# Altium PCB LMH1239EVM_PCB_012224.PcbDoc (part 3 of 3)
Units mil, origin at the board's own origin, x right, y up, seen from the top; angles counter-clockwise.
Board outline 4000 x 4500 mil, 4 copper layers (Top Layer, L02_GND, L03_PWR, Bottom Layer), stack 61.395 mil thick; 161 components, 103 nets, 483 pads, 593 vias.
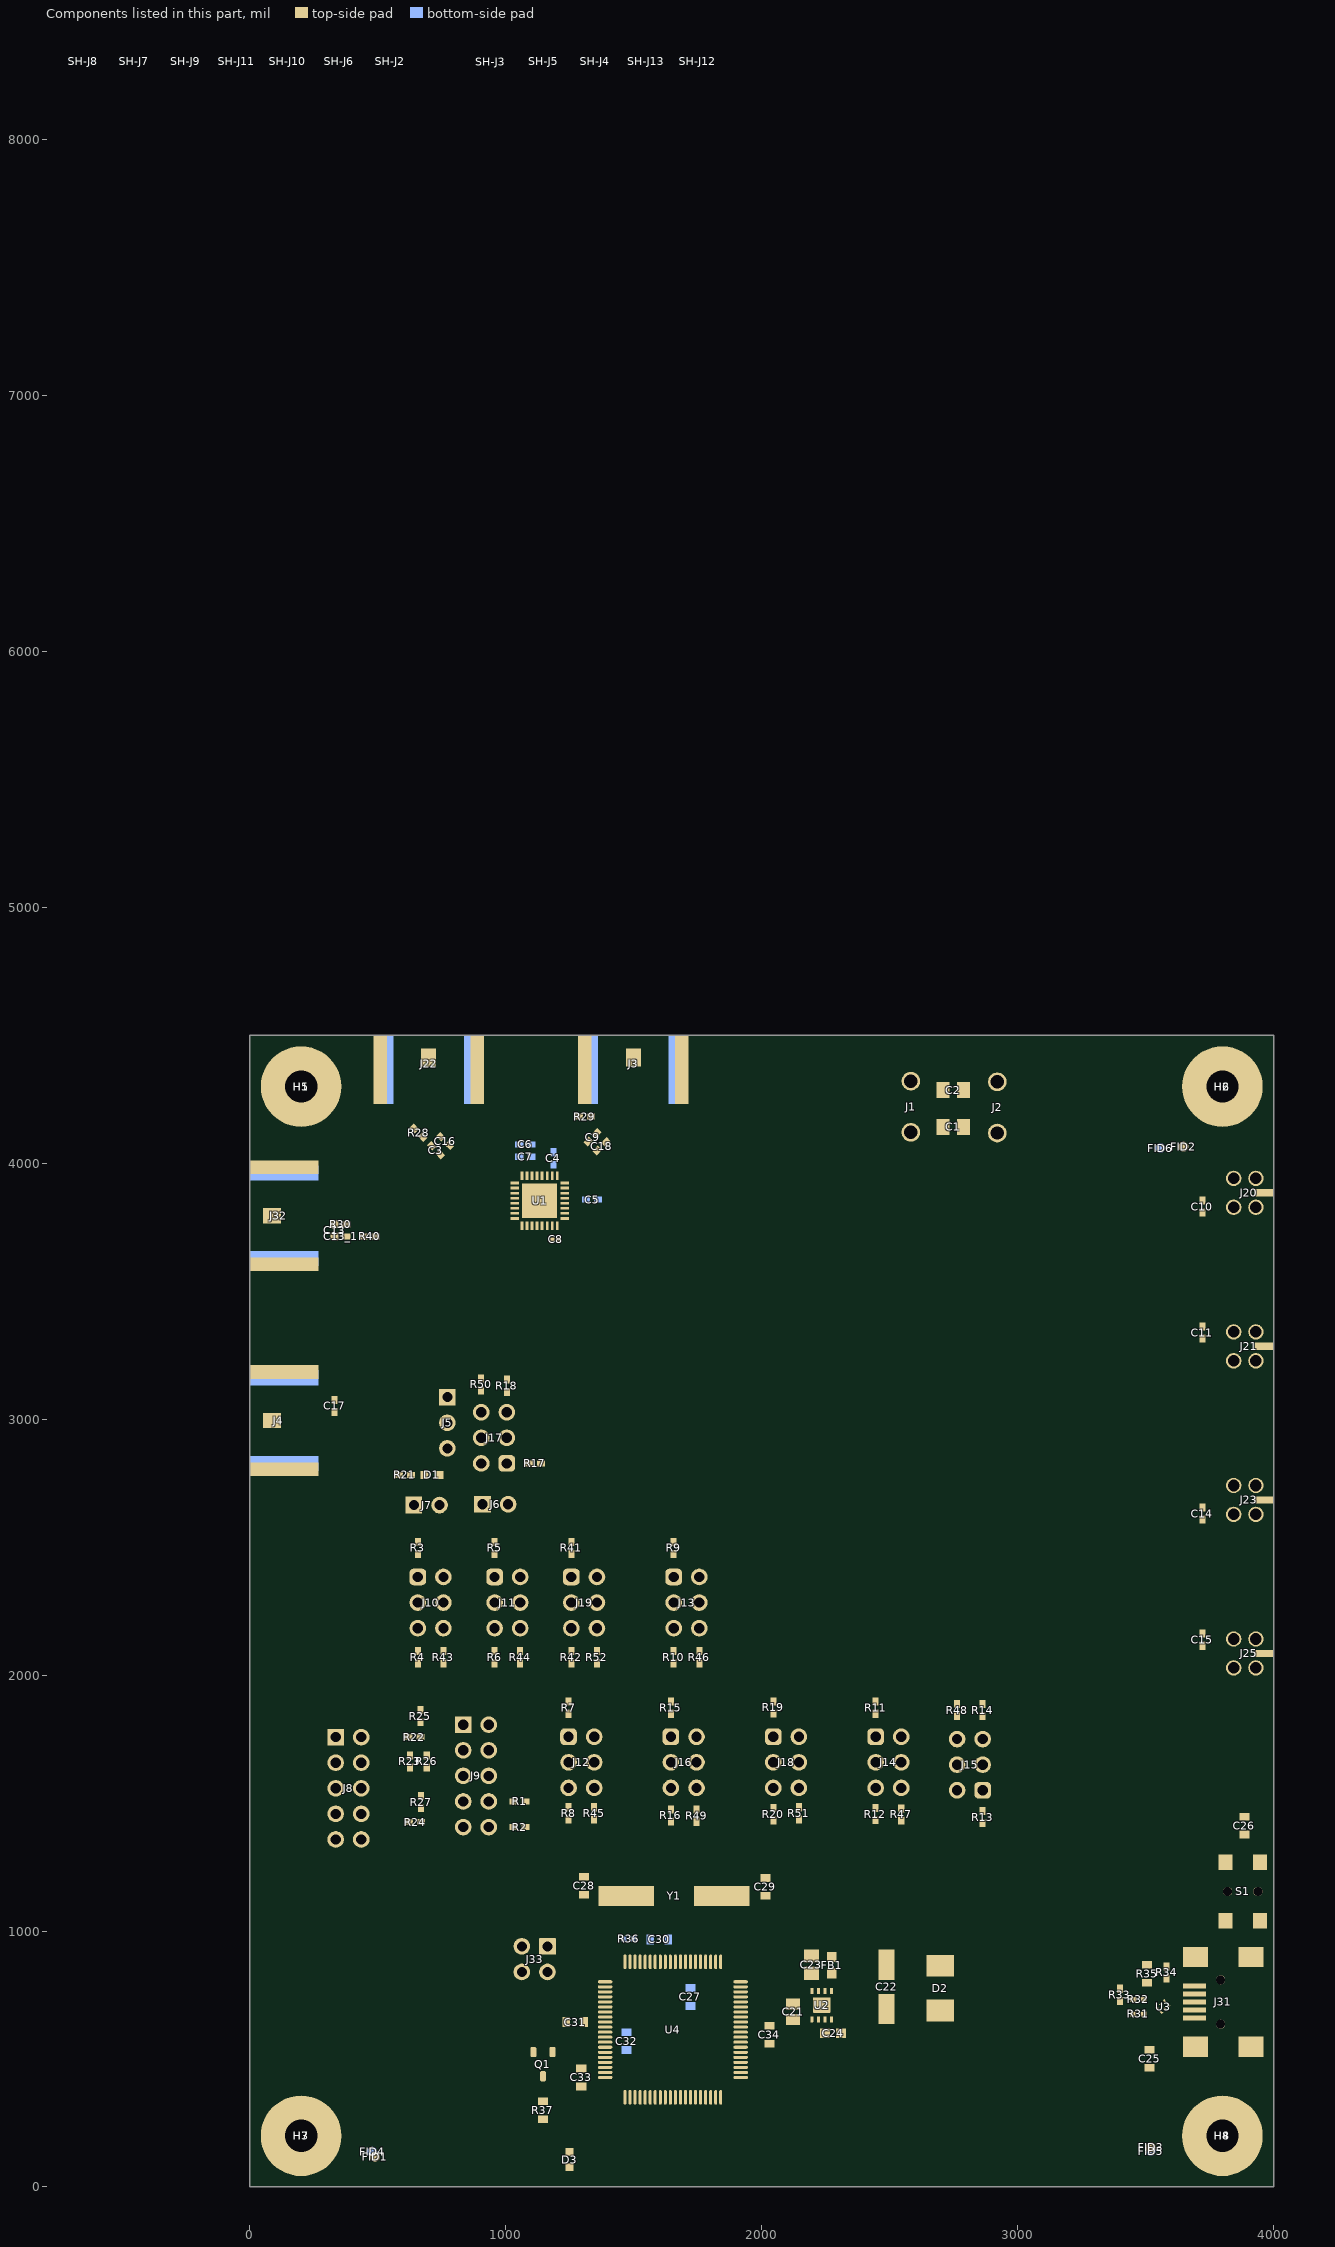
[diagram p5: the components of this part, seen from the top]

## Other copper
Top Layer:
  region net NetC17_2: 122.05,3024.71 122.05,3014.24 ccw(c139,3014.24) 139.8,2997.31 139.8,2993.03 ccw(c138.86,2976.25) 122.05,2976.28 122.05,2965.65 117.33,2965.65 cw(c117.33,2973.97) 109.02,2973.97 109.02,3011.68 cw(c122.05,3011.68)
  region net NetC13_2: 122.05,3824.71 122.05,3814.24 ccw(c139,3814.24) 139.8,3797.31 139.8,3793.03 ccw(c138.86,3776.25) 122.05,3776.28 122.05,3765.65 117.33,3765.65 cw(c117.33,3773.97) 109.02,3773.97 109.02,3811.68 cw(c122.05,3811.68)
  region net NetC16_2: 727.64,4377.95 717.18,4377.95 ccw(c717.18,4361) 700.25,4360.19 695.97,4360.19 ccw(c679.18,4361.13) 679.21,4377.94 668.59,4377.95 668.59,4382.66 cw(c676.9,4382.66) 676.9,4390.97 714.61,4390.97 cw(c714.61,4377.95)
  region net NetC18_2: 1527.64,4377.95 1517.18,4377.95 ccw(c1517.18,4361) 1500.25,4360.2 1495.97,4360.2 ccw(c1479.18,4361.14) 1479.21,4377.95 1468.59,4377.95 1468.59,4382.67 cw(c1476.9,4382.67) 1476.9,4390.98 1514.61,4390.98 cw(c1514.61,4377.95)
  region net VIN: 1212.58,3869.47 1293.89,3869.47 1298.54,3864.82 1298.54,3854.46 1292.78,3848.7 1278.57,3848.7 1268.83,3858.45 1212.58,3858.45
  region net OUT0_N: 3620.59,3570.56 3620.79,3581.36 3613.49,3580.36 3613.39,3571.56
  region net OUT0_P: 3620.59,3588.56 3620.79,3599.36 3613.49,3598.36 3613.39,3589.56
  pour cut-out: 1316.64,4213 1348.13,4213 1348.13,4153 1316.64,4153
  pour cut-out: 1206.28,3739.95 1206.28,3773.41 1175.57,3773.41 1175.57,3739.95
  pour cut-out: 1212.58,3799.4 1246.04,3799.4 1246.04,3830.1 1212.58,3830.1
  pour cut-out: 1212.58,3878.14 1246.04,3878.14 1246.04,3908.84 1212.58,3908.84
  pour cut-out: 1139.75,3932.76 1084.62,3932.76 1084.62,3970.36 1139.75,3970.36
  pour cut-out: 1015.63,3767.5 1015.63,3822.63 1053.23,3822.63 1053.23,3767.5
  pour cut-out: 1015.63,3885.61 1015.63,3940.74 1053.23,3940.74 1053.23,3885.61
  pour cut-out: 1171.97,3711.12 1216.14,3711.12 1216.14,3694.56 1171.97,3694.56
  pour cut-out: 665.25,4071.08 642.98,4093.35 685.41,4135.77 707.67,4113.5
  pour cut-out: 362.06,3744.64 393.55,3744.64 393.55,3684.64 362.06,3684.64
  pour cut-out: 428.27,3744.64 459.76,3744.64 459.76,3684.64 428.27,3684.64
  pour cut-out: 360.56,3091.47 360.56,3012.73 300.56,3012.73 300.56,3091.47
  pour cut-out: 360.56,3777.64 360.56,3698.89 300.56,3698.89 300.56,3777.64
  pour cut-out: 1422.97,4073.78 1367.29,4018.1 1324.86,4060.52 1380.54,4116.2
  pour cut-out: 1387.61,4109.13 1331.93,4053.45 1289.51,4095.88 1345.19,4151.56
  pour cut-out: 720.34,4100.84 776.02,4045.16 733.59,4002.74 677.91,4058.42
  pour cut-out: 755.69,4136.2 811.37,4080.52 768.95,4038.09 713.27,4093.77
  region net SDI_OUT+: 430.6,3392.33 430.52,3388.03 433.58,3388.45 433.61,3391.91
  region net VIN: 1147.53,3961.64 1147.53,3971.13 1161.78,3985.38 1166,3985.23 1171.49,3990.73 1171.49,3997.26 1166.46,4002.28 1156.27,4002.28 1136.05,3982.07 1136.05,3934.96 1147.53,3934.96 1147.53,3961.36
  region net VDD_LDO: 1077.13,3934.81 1077.13,3970.38 1071.76,3975.75 1049.35,3975.75 1030.68,3994.42 1030.68,4000.16 1035.03,4004.51 1057.09,4004.51 1088.16,3973.44 1088.16,3934.81
  region net VBUS: 3533.8,715.6 3525.86,715.56 3519.9,709.6 3519.9,701.4 3529.69,691.61 3544.43,691.63 3547.2,691.6 3553.5,697.9 3553.5,701.2 3539.1,715.6
  region net NetJ31_6: 3956.5,942 3583.4,942 3568.6,927.2 3568.6,847.2 3570.4,845.4 3834.3,845.4 3857.6,822.1 3857.6,626.1 3821.2,589.7 3642.2,589.7 3636.6,584.1 3636.6,509.3 3642.7,503.2 3642.7,502.5 3957,502.5 3970.9,516.4 3970.9,927.6
  region net NetC23_1: 2296,859 2293.51,861.49 2164.49,861.49 2162,859 2162,755 2165,752 2201,752 2202,753 2202,777.4 2210.8,786.2 2260.5,786.2 2266.1,780.6 2266.1,754.9 2267.7,753.3 2291.7,753.3 2296,757.6
  region net OUT1_N: 3620.59,2370.56 3620.79,2381.36 3613.49,2380.36 3613.39,2371.56
  region net OUT1_P: 3620.59,2388.56 3620.79,2399.36 3613.49,2398.36 3613.39,2389.56
  region net SDI_OUT-: 430.6,3402.33 430.52,3398.03 433.57,3398.45 433.61,3401.91
  region net GND: 534.56,4473.04 534.93,4473.4 534.93,4496.06 481.78,4496.06 481.78,4472.55 534.93,4472.55
  region net GND: 914.09,4473.04 914.45,4473.4 914.45,4496.06 861.31,4496.06 861.31,4472.55 914.45,4472.55
  region net GND: 2741.3,759.4 2459.1,759.4 2451.3,751.6 2451.3,617.1 2466.2,602.2 2740.1,602.2 2755.4,617.5 2755.4,745.3
  region net GND: 3620.6,775.3 3489,775.3 3481.15,783.15 3481.15,822.1 3490.85,831.8 3570.4,831.8 3733.6,831.8 3738.2,827.2 3738.2,776.6 3736.9,775.3
  region net GND: 3974.51,3124.93 3999.01,3124.93 3999.01,3262.81 3974.51,3262.81
  region net GND: 3974.51,3444.93 3999.01,3444.93 3999.01,3307.06 3974.51,3307.06
  region net GND: 3974.51,2244.94 3999.01,2244.94 3999.01,2107.06 3974.51,2107.06
  region net GND: 3974.51,1924.94 3999.01,1924.94 3999.01,2062.81 3974.51,2062.81
  region net GND: 3974.51,2524.94 3999.01,2524.94 3999.01,2662.81 3974.51,2662.81
  region net GND: 3974.51,2844.94 3999.01,2844.94 3999.01,2707.06 3974.51,2707.06
  region net 3P3V: 1979.95,592.45 1979.95,603.25 1997.6,620.9 1997.6,663.9 2011,677.3 2088.4,677.3 2178.6,677.3 2185.7,670.2 2198.9,670.2 2202.3,666.8 2202.3,604 2189.3,591 2007.5,591 2001,584.5 1987.9,584.5
  region: 124.03,2854.15 124.03,2865.18 124.03,2876.21
  pour cut-out: 3751.5,2670.69 3751.5,2591.94 3691.5,2591.94 3691.5,2670.69
  pour cut-out: 3751.5,2177.93 3751.5,2099.19 3691.5,2099.19 3691.5,2177.93
  pour cut-out: 3751.5,3377.93 3751.5,3299.19 3691.5,3299.19 3691.5,3377.93
  pour cut-out: 3751.5,3870.69 3751.5,3791.94 3691.5,3791.94 3691.5,3870.69
  text ".Layer_Name" at -923,-6999.16 h60
L02_GND:
  region net GND: 3968,2244.94 4000.01,2244.94 4000.01,2102.19 3968,2102.18
  region net GND: 3968,1924.94 4000.01,1924.94 4000.01,2067.69 3968,2067.69
  region net GND: 3968,2844.94 4000.01,2844.94 4000.01,2702.19 3968,2702.18
  region net GND: 3968,2524.94 4000.01,2524.94 4000.01,2667.69 3968,2667.69
  region net GND: 3968,3444.93 4000.01,3444.93 4000.01,3302.18 3968,3302.18
  region net GND: 3968,3124.93 4000.01,3124.93 4000.01,3267.68 3968,3267.69
  region net GND: 3968,3724.93 4000.01,3724.93 4000.01,3867.68 3968,3867.69
  region net GND: 3968,4044.93 4000.01,4044.93 4000.01,3902.18 3968,3902.18
  pour cut-out: 1316.64,4213 1348.13,4213 1348.13,4153 1316.64,4153
  pour cut-out: 1015.63,3885.61 1015.63,3940.74 1053.23,3940.74 1053.23,3885.61
  pour cut-out: 1015.63,3767.5 1015.63,3822.63 1053.23,3822.63 1053.23,3767.5
  pour cut-out: 1139.75,3932.76 1084.62,3932.76 1084.62,3970.36 1139.75,3970.36
  pour cut-out: 1212.58,3878.14 1246.04,3878.14 1246.04,3908.84 1212.58,3908.84
  pour cut-out: 1212.58,3799.4 1246.04,3799.4 1246.04,3830.1 1212.58,3830.1
  pour cut-out: 1206.28,3739.95 1206.28,3773.41 1175.57,3773.41 1175.57,3739.95
  pour cut-out: 1171.97,3711.12 1216.14,3711.12 1216.14,3694.56 1171.97,3694.56
  pour cut-out: 665.25,4071.08 642.98,4093.35 685.41,4135.77 707.67,4113.5
  pour cut-out: 362.06,3744.64 393.55,3744.64 393.55,3684.64 362.06,3684.64
  pour cut-out: 428.27,3744.64 459.76,3744.64 459.76,3684.64 428.27,3684.64
  pour cut-out: 360.56,3091.47 360.56,3012.73 300.56,3012.73 300.56,3091.47
  pour cut-out: 360.56,3777.64 360.56,3698.89 300.56,3698.89 300.56,3777.64
  pour cut-out: 1387.61,4109.13 1331.93,4053.45 1289.51,4095.88 1345.19,4151.56
  pour cut-out: 1422.97,4073.78 1367.29,4018.1 1324.86,4060.52 1380.54,4116.2
  pour cut-out: 755.69,4136.2 811.37,4080.52 768.95,4038.09 713.27,4093.77
  pour cut-out: 720.34,4100.84 776.02,4045.16 733.59,4002.74 677.91,4058.42
  pour cut-out: 3922,2067.69 3999,2067.69 3999,2102.19 3922,2102.19
  pour cut-out: 3922,3867.68 3999,3867.68 3999,3902.18 3922,3902.18
  pour cut-out: 3922,3267.68 3999,3267.68 3999,3302.18 3922,3302.18
  pour cut-out: 3922,2667.69 3999,2667.69 3999,2702.19 3922,2702.19
  pour cut-out: 3751.5,2177.93 3751.5,2099.19 3691.5,2099.19 3691.5,2177.93
  pour cut-out: 3751.5,2670.69 3751.5,2591.94 3691.5,2591.94 3691.5,2670.69
  pour cut-out: 3751.5,3870.69 3751.5,3791.94 3691.5,3791.94 3691.5,3870.69
  pour cut-out: 3751.5,3377.93 3751.5,3299.19 3691.5,3299.19 3691.5,3377.93
  text ".Layer_Name" at -897.39,-6995.96 h60
L03_PWR:
  region net GND: 3968,2244.94 4000.01,2244.94 4000.01,2102.19 3968,2102.18
  region net GND: 3968,1924.94 4000.01,1924.94 4000.01,2067.69 3968,2067.69
  region net GND: 3968,2844.94 4000.01,2844.94 4000.01,2702.19 3968,2702.18
  region net GND: 3968,2524.94 4000.01,2524.94 4000.01,2667.69 3968,2667.69
  region net GND: 3968,3444.93 4000.01,3444.93 4000.01,3302.18 3968,3302.18
  region net GND: 3968,3124.93 4000.01,3124.93 4000.01,3267.68 3968,3267.69
  region net GND: 3968,3724.93 4000.01,3724.93 4000.01,3867.68 3968,3867.69
  region net GND: 3968,4044.93 4000.01,4044.93 4000.01,3902.18 3968,3902.18
  pour cut-out: 1316.64,4213 1348.13,4213 1348.13,4153 1316.64,4153
  pour cut-out: 665.25,4071.08 642.98,4093.35 685.41,4135.77 707.67,4113.5
  pour cut-out: 362.06,3744.64 393.55,3744.64 393.55,3684.64 362.06,3684.64
  pour cut-out: 428.27,3744.64 459.76,3744.64 459.76,3684.64 428.27,3684.64
  pour cut-out: 3751.5,2177.93 3751.5,2099.19 3691.5,2099.19 3691.5,2177.93
  pour cut-out: 3751.5,2670.69 3751.5,2591.94 3691.5,2591.94 3691.5,2670.69
  pour cut-out: 3751.5,3377.93 3751.5,3299.19 3691.5,3299.19 3691.5,3377.93
  pour cut-out: 3751.5,3870.69 3751.5,3791.94 3691.5,3791.94 3691.5,3870.69
  pour cut-out: 360.56,3091.47 360.56,3012.73 300.56,3012.73 300.56,3091.47
  pour cut-out: 360.56,3777.64 360.56,3698.89 300.56,3698.89 300.56,3777.64
  pour cut-out: 1387.61,4109.13 1331.93,4053.45 1289.51,4095.88 1345.19,4151.56
  pour cut-out: 1422.97,4073.78 1367.29,4018.1 1324.86,4060.52 1380.54,4116.2
  pour cut-out: 755.69,4136.2 811.37,4080.52 768.95,4038.09 713.27,4093.77
  pour cut-out: 720.34,4100.84 776.02,4045.16 733.59,4002.74 677.91,4058.42
  pour cut-out: 3922,2067.69 3999,2067.69 3999,2102.19 3922,2102.19
  pour cut-out: 3922,3867.68 3999,3867.68 3999,3902.18 3922,3902.18
  pour cut-out: 3922,3267.68 3999,3267.68 3999,3302.18 3922,3302.18
  pour cut-out: 3922,2667.69 3999,2667.69 3999,2702.19 3922,2702.19
  text ".Layer_Name" at -929.4,-6999.16 h60
Bottom Layer:
  region net GND: 3968,2244.94 4000.01,2244.94 4000.01,2067.69 3968,2067.68
  region net GND: 3968,1924.94 4000.01,1924.94 4000.01,2067.69 3968,2067.69
  region net GND: 3968,2844.94 4000.01,2844.94 4000.01,2667.69 3968,2667.68
  region net GND: 3968,2524.94 4000.01,2524.94 4000.01,2667.69 3968,2667.69
  region net GND: 3968,3444.93 4000.01,3444.93 4000.01,3267.68 3968,3267.68
  region net GND: 3968,3124.93 4000.01,3124.93 4000.01,3267.68 3968,3267.69
  region net GND: 3968,3724.93 4000.01,3724.93 4000.01,3867.68 3968,3867.69
  region net GND: 3968,4044.93 4000.01,4044.93 4000.01,3867.68 3968,3867.68
  region net VIN: 1147.57,3973.3 1142.24,3978.63 1142.24,3988.4 1166.26,4012.42 1197.31,4012.42 1199.17,4010.56 1199.17,3981.48 1190.87,3973.18
  region net VDD_LDO: 1068.76,3981.27 1068.76,4086.15 1067.7,4087.21 1036.2,4087.21 1030.99,4081.99 1030.99,3993.28 1050.79,3973.48 1060.97,3973.48
  text ".Layer_Name" at -923,-6999.16 h60
Multi-Layer:
  pour cut-out: 18.16,2842.68 140,2945.18 140,3045.18 18.16,3147.68
  pour cut-out: 24.03,3397.39 24.03,3412.82 28.92,3417.71 331.43,3417.71 336.64,3412.5 336.64,3398.7 330.42,3392.47 28.95,3392.47
  pour cut-out: 33.87,2679.83 261.23,2679.83 456.26,2874.86 456.26,3187.04 1037.49,3768.27 1048.36,3768.27 1060.78,3755.85 481,3176.06 481,2867.36 275.57,2661.93 20.46,2661.93 20.46,2673.32 27.03,2679.9 31.65,2679.9
  pour cut-out: 273.61,4085.89 649.01,3710.49 810.44,3710.49 966.51,3866.57 966.51,3874.44 962.08,3878.86 665.76,3878.86 382.76,4161.87 382.76,4471.59 372.8,4481.55 38.16,4481.55 17.06,4460.46 17.06,4071.71 24.91,4071.71 39.09,4085.89
  pour cut-out: 1070.42,4016.85 1070.42,4090.08 1079.36,4099.01 1139.35,4099.01 1172.83,4132.49 1172.83,4475.27 1168.48,4479.63 1027.18,4479.63 1021.7,4474.15 1021.7,4018.88 1036.06,4004.51 1058.09,4004.51
  pour cut-out: 1773.57,4469.38 1773.57,4255.83 1521.47,4003.73 1302.15,4003.73 1300.18,4001.77 1300.18,3992.95 1303.06,3990.07 1530.34,3990.07 1790.04,4249.77 1790.04,4474.25 1784.55,4479.74 1776.24,4479.74 1773.42,4476.93 1773.42,4469.96
  pour cut-out: 18.16,3642.68 140,3745.18 140,3845.18 18.16,3947.68
  pour cut-out: 545.62,4479.87 648.12,4358.04 748.12,4358.04 850.62,4479.87
  pour cut-out: 1345.62,4479.87 1448.12,4358.04 1548.12,4358.04 1650.62,4479.87

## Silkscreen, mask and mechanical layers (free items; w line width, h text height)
Top Overlay:
  lines w5: 681,2741.33 701.87,2741.33 ; 701.78,2758.96 719.46,2741.29 ; 701.87,2758.96 701.87,2723.7 719.46,2741.29 ; 719.46,2723.65 719.46,2758.92 ; 732.87,2741.29 719.46,2741.29 ; 1184.37,95.11 1202.04,112.79 ; 1184.37,95.2 1219.63,95.2 1202.04,112.79 ; 1184.41,112.79 1219.68,112.79 ; 1202,74.33 1202,95.2 ; 1202.04,126.2 1202.04,112.79 ; 2800.37,784.11 2818.04,801.79 ; 2800.37,784.2 2835.63,784.2 2818.04,801.79 ; 2800.41,801.79 2835.68,801.79 ; 2818,763.33 2818,784.2 ; 2818.04,815.2 2818.04,801.79 ; 3451.18,751.01 3451.18,807.44 ; 3455.47,651.94 3455.47,658.43 ; 3477.55,570.75 3541.04,657.11
  lines w10: 2467,965.33 2509,965.33 ; 2488,944.33 2488,986.33
  text "GND" at 2501,4160 h60 r90
  text "VIN" at 3074,4158 h60 r90
  text "LMH1239 EVM 12G Dual Long Reach Equalizer" at 1883.92,2283.62 h90
  text "'.PRJ_Number'" at 2521.35,2169.38 h90
  text ".Layer_Name" at -923,-6999.16 h60
Bottom Overlay:
  drawing of 2342 lines, arcs and shapes, not listed
  text "H: Tie 1K-Ohm to VIN" at 3614.6,3899.11 h40
  text "F:  Float - No connection" at 3615.83,3837.46 h40
  text "R: Tie 20K-Ohm to VSS" at 3616.76,3777.07 h40
  text "L: Tie 1K-Ohm to VSS" at 3616.81,3711.95 h40
  text "OUT_CTRL J14" at 3736.14,3597.81 h40
  text "H and F: OUT0, OUT1, SDI_OUT EQ and Reclocker Enabled" at 3736.14,3528.84 h40
  text "R: OUT0/SDI_OUT EQ and Reclocker Enabled OUT1: Recovered Clock if enabled through OUT0_OUT1_SEL" at 3736.14,3463.81 h40
  text "L: OUT0/SDI_OUT and OUT1 Equalized Data (CTLE/DFE Enabled) Reclocker bypassed" at 3736.14,3396.89 h40
  text "Note: L Mode - Reclocker bypassed but not powered down - needed for DFE operation" at 3736.14,3328.18 h40
  text "LOOP_BW_SEL J11" at 3727.77,2914.48 h40
  text "H: 13MHz/7MHz/5MHz/3MHz/1MHz" at 3727.77,2836.12 h40
  text "F: 13MHz/7MHz/5MHz/3MHz/1MHz" at 3727.77,2763 h40
  text "R: 800KHz/437KHz/312KHz/187KHz/62KHz" at 3727.77,2694.94 h40
  text "L: 400KHz/219KHz/156KHz/94KHz/31KHz" at 3727.77,2618.39 h40
  text "Note: These are for 12G/6G/3G/HD/SD Data rates. External Caps are needed for H, R, and L cases" at 3727.77,2547.97 h40
  text "H: 410 mVpp, 0dB DEM" at 2614.79,2155.76 h40
  text "VOD_DEM_SEL J12" at 3252.36,2150.01 h40
  text "F: 560 mVpp, -0.9dB" at 2614.79,2096.38 h40
  text "R: 635 mVpp, -2.4dB" at 2614.79,2030.86 h40
  text "L: 810 mVpp, -4.0dB" at 2614.79,1968.16 h40
  text "MODE_SEL J13" at 3310.62,1429.93 h40
  text "H: Forced Power Save Mode" at 2771.04,1427.51 h40
  text "F: Select SPI interface for register access" at 2771.04,1373.41 h40
  text "R: Reserved - do not use" at 2771.04,1319.18 h40
  text "L: Select SMBus interface for register access" at 2771.04,1266.89 h40
  text "OUT0_ OUT1_SEL" at 3329.87,1175.48 h40
  text "H: OUT0 and OUT1 Muted" at 2771.04,1167.85 h40
  text "F and L:OUT0 enabled OUT1 Muted" at 2771.04,1113.22 h40
  text "R: OUT0 and OUT1 enabled" at 2771.04,1059.72 h40
  text "H: About + 5% nominal" at 2886.57,917.53 h40
  text "SDI_VOD J15" at 3368.64,916.1 h40
  text "F: 800 mVpp (nominal)" at 2886.47,861.08 h40
  text "R: About + 10% of nominal" at 2885.6,804.43 h40
  text "L: About -5% nominal" at 2885.6,749.35 h40
  text "305-PD-23-1033" at 839.22,668.53 h50
  text "JAN 2024" at 839.13,577.93 h50
  text "ADDR0/1 J16/J17" at 2957.28,570.9 h40
  text "L/L: xx" at 2355.84,565.75 h40
  text "F/L:" at 2353.36,499.74 h40
  text "Refer to the data sheet for additional settings" at 2355.77,439.91 h40
  text "H: SDI_OUT Disabled(Default internally pulled high)" at 2355.84,366.37 h40
  text "SDI_OUT_ENA J18" at 2970.82,363.29 h40
  text "F and R: Do not use" at 2355.84,300.52 h40
  text "L: SDI_OUT Enabled" at 2354.33,238.07 h40
  text "SDI_IN_SEL J19" at 2957.28,148.34 h40
  text "H and F: SDI_IN0 selected" at 2355.84,146.35 h40
  text "R and L: SDI_IN1 selected" at 2353.58,74.09 h40
  text ".Layer_Name" at -923,-6999.16 h60
Top Paste:
  text ".Layer_Name" at -923,-6999.16 h60
Bottom Paste:
  region: 3931,3798.43 cw(c3931,3828.43) 3901,3828.43 cw(c3931,3828.43) 3931,3858.43 cw(c3931,3828.43) 3961,3828.43 cw(c3931,3828.43)
  region: 3931,3911.43 cw(c3931,3941.43) 3901,3941.43 cw(c3931,3941.43) 3931,3971.43 cw(c3931,3941.43) 3961,3941.43 cw(c3931,3941.43)
  region: 3844,3798.43 cw(c3844,3828.43) 3814,3828.43 cw(c3844,3828.43) 3844,3858.43 cw(c3844,3828.43) 3874,3828.43 cw(c3844,3828.43)
  region: 3844,3911.43 cw(c3844,3941.43) 3814,3941.43 cw(c3844,3941.43) 3844,3971.43 cw(c3844,3941.43) 3874,3941.43 cw(c3844,3941.43)
  region: 3931,3198.43 cw(c3931,3228.43) 3901,3228.43 cw(c3931,3228.43) 3931,3258.43 cw(c3931,3228.43) 3961,3228.43 cw(c3931,3228.43)
  region: 3931,3311.43 cw(c3931,3341.43) 3901,3341.43 cw(c3931,3341.43) 3931,3371.43 cw(c3931,3341.43) 3961,3341.43 cw(c3931,3341.43)
  region: 3844,3311.43 cw(c3844,3341.43) 3814,3341.43 cw(c3844,3341.43) 3844,3371.43 cw(c3844,3341.43) 3874,3341.43 cw(c3844,3341.43)
  region: 3844,3198.43 cw(c3844,3228.43) 3814,3228.43 cw(c3844,3228.43) 3844,3258.43 cw(c3844,3228.43) 3874,3228.43 cw(c3844,3228.43)
  region: 3931,2711.44 cw(c3931,2741.44) 3901,2741.44 cw(c3931,2741.44) 3931,2771.44 cw(c3931,2741.44) 3961,2741.44 cw(c3931,2741.44)
  region: 3931,2598.44 cw(c3931,2628.44) 3901,2628.44 cw(c3931,2628.44) 3931,2658.44 cw(c3931,2628.44) 3961,2628.44 cw(c3931,2628.44)
  region: 3844,2711.44 cw(c3844,2741.44) 3814,2741.44 cw(c3844,2741.44) 3844,2771.44 cw(c3844,2741.44) 3874,2741.44 cw(c3844,2741.44)
  region: 3844,2598.44 cw(c3844,2628.44) 3814,2628.44 cw(c3844,2628.44) 3844,2658.44 cw(c3844,2628.44) 3874,2628.44 cw(c3844,2628.44)
  region: 3931,2111.44 cw(c3931,2141.44) 3901,2141.44 cw(c3931,2141.44) 3931,2171.44 cw(c3931,2141.44) 3961,2141.44 cw(c3931,2141.44)
  region: 3931,1998.44 cw(c3931,2028.44) 3901,2028.44 cw(c3931,2028.44) 3931,2058.44 cw(c3931,2028.44) 3961,2028.44 cw(c3931,2028.44)
  region: 3844,2111.44 cw(c3844,2141.44) 3814,2141.44 cw(c3844,2141.44) 3844,2171.44 cw(c3844,2141.44) 3874,2141.44 cw(c3844,2141.44)
  region: 3844,1998.44 cw(c3844,2028.44) 3814,2028.44 cw(c3844,2028.44) 3844,2058.44 cw(c3844,2028.44) 3874,2028.44 cw(c3844,2028.44)
  text ".Layer_Name" at -923,-6999.16 h60
Top Solder:
  text ".Layer_Name" at -923,-6999.16 h60
  text ".Layer_Name" at -923,-6999.16 h60
Bottom Solder:
  text ".Layer_Name" at -923,-6999.16 h60
Drill Guide:
  text ".Layer_Name" at -923,-6999.16 h60
M1 Board Outline:
  lines w10: 0,2300 0,2400 ; 4000,2300 4000,2400 ; 0,0 0,4500 4000,4500 4000,0 0,0
  text ".Layer_Name" at -923,-6999.16 h60
M2 Board Dimensions:
  rectangle: -1500,-6415.67 -1375,-6290.67
  rectangle: -1375,-6540.67 -1000,-6415.67
  lines w7: -1500,-6415.67 -500,-6415.67 ; -1375,-6540.67 -1375,-6290.67 ; -1250,-6540.67 -1250,-6290.67 ; -1000,-6540.67 -1000,-6290.67 ; -750,-6540.67 -750,-6290.67 ; -1500,-6540.67 -500,-6540.67 -500,-6290.67 -1500,-6290.67 -1500,-6540.67
  text ".Layer_Name" at -923,-6999.16 h60
M3 3D STEP Top:
  text ".Layer_Name" at -923,-6999.16 h60
M4 3D STEP Bottom:
  text ".Layer_Name" at -923,-6999.16 h60
M5 Assembly Top:
  lines w10: -1792,-7070.84 4808,-7070.84 ; -1792,-6867.5 4810,-6867.5 ; -1792,-6664.17 -1792,-7274.17 2213,-7274.17 4810,-7274.17 4810,-6664.17 -1791.5,-6664.17 -1791.5,-7274.17 -216,-7274.17 ; 673,-7274.17 673,-6664.17 ; 1940,-6867.5 1940,-6664.17 ; 2780,-6867.5 2780,-6664.17 ; 3402,-7280.67 3402,-7077.84
  text "COMPONENTS MARKED 'DNP' SHOULD NOT BE POPULATED." at -346.5,-6459.17 h60
  text "ASSEMBLY VARIANT:" at -347,-6574.67 h60
  text ".VariantName" at 689,-6574.67 h60
  text "PCB VIEWED FROM TOP SIDE" at -1728.5,-6796.34 h60
  text "BOARD #:" at 748,-6796.34 h60
  text ".PRJ_Number" at 1293.5,-6796.34 h60
  text "REV:" at 2138,-6796.34 h60
  text ".PCB_Rev" at 2429.5,-6796.34 h60
  text "SVN REV:" at 2976,-6796.34 h60
  text ".VersionControl_RevNumber" at 3482,-6796.34 h60
  text "TID #:" at 748,-6999.67 h60
  text ".TID" at 1293.5,-6999.67 h60
  text "PLOT NAME =" at -1728.5,-7205.01 h60
  text ".plot_File_Name" at -923,-7205.01 h60
  text "GENERATED    :" at 750,-7205.01 h60
  text ".Print_Date" at 1619.5,-7205.01 h60
  text ".Print_Time" at 2348.5,-7205.01 h60
  text "TEXAS INSTRUMENTS" at 3613,-7205.01 h60
M6 Assembly Bottom:
  lines w10: -1792.5,-6868 4809.5,-6868 ; -1790.5,-7071.34 4809.5,-7071.34 ; -384.5,-7281.17 -384.5,-7078.34 ; 237.5,-6868 237.5,-6664.67 ; 1077.5,-6868 1077.5,-6664.67 ; 2344.5,-7274.67 2344.5,-6664.67 ; 3233.5,-7274.67 4809,-7274.67 4809,-6664.67 -1792.5,-6664.67 -1792.5,-7274.67 804.5,-7274.67 4809.5,-7274.67 4809.5,-6664.67
  text "COMPONENTS MARKED 'DNP' SHOULD NOT BE POPULATED." at 4602,-6458.67 h60
  text ".VariantName" at 3558,-6574.67 h60
  text "ASSEMBLY VARIANT:" at 4597,-6574.67 h60
  text ".VersionControl_RevNumber" at -464.5,-6796.84 h60
  text "SVN REV:" at 41.5,-6796.84 h60
  text ".PCB_Rev" at 588,-6796.84 h60
  text "REV:" at 879.5,-6796.84 h60
  text ".PRJ_Number" at 1724,-6796.84 h60
  text "BOARD #:" at 2269.5,-6796.84 h60
  text "PCB VIEWED FROM BOTTOM SIDE" at 4746,-6796.84 h60
  text ".TID" at 1724,-7000.17 h60
  text "TID #:" at 2269.5,-7000.17 h60
  text "TEXAS INSTRUMENTS" at -595.5,-7205.51 h60
  text ".Print_Time" at 669,-7205.51 h60
  text ".Print_Date" at 1398,-7205.51 h60
  text "GENERATED    :" at 2267.5,-7205.51 h60
  text ".plot_File_Name" at 3940.5,-7205.51 h60
  text "PLOT NAME =" at 4746,-7205.51 h60
M9 Title Sheet:
  drawing of 57 lines, arcs and shapes, not listed
  text "1" at -760.16,5895.83 h70
  text "2" at 1735.5,5895.83 h70
  text "3" at 4224.84,5895.83 h70
  text "4" at 6731.51,5895.83 h70
  text "5" at 9230.5,5895.83 h70
  text "6" at 11735.5,5895.83 h70
  text "A" at -1916.5,752.83 h70
  text "A" at 12883.5,752.83 h70
  text "B" at -1916.5,-1627.17 h70
  text "B" at 12883.5,-1627.17 h70
  text "C" at -1916.5,-4002.17 h70
  text "C" at 12883.5,-4002.17 h70
  text "PROJECT TITLE:" at 9843.5,-5863.17 h45
  text "LMH1239EVM_Rev1" at 9893.5,-5996.5 h70
  text "DESIGNED FOR:" at 9843.5,-6164.17 h45
  text ".PRJ_Customer" at 9893.5,-6304.17 h70
  text "D" at -1916.5,-6372.17 h70
  text "D" at 12883.5,-6372.17 h70
  text "FILE NAME:" at 9843.5,-6464.17 h45
  text ".PCB_File_Name_No_Path" at 9860.19,-6589.48 h65
  text "Texas Instruments (TI) and/or its licensors do not warrant the accuracy or completeness of this specification" at 4874,-6746.01 h45
  text "ENGINEER:" at 9843.5,-6754.17 h45
  text "LAYOUT BY:" at 11348.5,-6754.17 h45
  text "or any information contained therein. TI and/or its licensors do not warrant that this design will meet" at 4829.02,-6858.67 h45
  text ".PRJ_Engineer" at 9893.5,-6909.16 h70
  text ".PCB_Layout" at 11399,-6909.16 h70
  text "the specifications, will be suitable for your application or fit for any particular purpose, or will operate in" at 4829.02,-6971.34 h45
  text ".Layer_Name" at -923,-6999.16 h60
  text "ALTIUM DESIGNER VERSION:" at 11348.5,-7064.17 h45
  text "an implementation. TI and/or its licensors do not warrant that the design is production worthy. You should" at 4829.02,-7084.01 h45
  text "completely validate and test your design implementation to confirm the system functionality for your application." at 4874,-7196.67 h45
  text ".print_Scale" at 9893.5,-7197.5 h70
  text ".Application_BuildNumber" at 11399,-7197.5 h70
  text "1" at -760.16,-7404.17 h70
  text "2" at 1735.5,-7404.17 h70
  text "3" at 4224.84,-7404.17 h70
  text "4" at 6731.51,-7404.17 h70
  text "5" at 9230.5,-7404.17 h70
  text "6" at 11735.5,-7404.17 h70
M10 Fab Notes:
  drawing of 189 lines, arcs and shapes, not listed
  text "IMPEDANCE DETAILS." at 4715.41,879.28 h75
  text "1. ALL 3.5 MIL TRACES WITH 6.5 MIL AIRGAP ON TOP LAYER" at 4667.81,697.31 h75
  text "NEED 135 ohm +/-5% IMPEDANCE WITH 6.6 MIL COPLANAR SPACING" at 4805.93,523.78 h75
  text "2. ALL 9.13 MIL TRACES WITH 8.87 MIL AIRGAP ON TOP LAYER" at 4657.81,359.65 h75
  text "DESIGN INFORMATION" at 10882.02,215.5 h60
  text "NEED 100 ohm +/-5% IMPEDANCE WITH 8.435 MIL COPLANAR SPACING" at 4805.93,196.13 h75
  text "3.5" at 11279.36,84.28 h60
  text "MIN. TRACK WIDTH:" at 10237.46,83.38 h60
  text "MIL" at 11488.46,83.38 h60
  text "3. ALL 4.3 MIL TRACES ON TOP LAYER NEED 75 ohm +/-5% IMPEDANCE" at 4667.81,-22.87 h75
  text "5.5" at 11276.68,-38.1 h60
  text "MIN. CLEARANCE:" at 10237.46,-40.75 h60
  text "MIL" at 11488.46,-40.75 h60
  text "MIN. VIA PAD SIZE:" at 10237.46,-164.87 h60
  text "MIL" at 11488.46,-164.87 h60
  text "16" at 11323,-168.67 h60
  text "WITH 8 MIL COPLANAR SPACING" at 4805.93,-195.94 h75
  text "0.05mm (2MIL)" at 10932.46,-294.77 h60
  text "MINIMUM ANNULAR RING" at 9908.23,-303 h60
  text "EXTERNAL" at 11640.46,-303 h60
  text "PER" at 10108.23,-413.12 h60
  text "IPC-D-275 CLASS 2 LEVEL C" at 10328.23,-413.13 h60
  text "4. ALL 10.96 MIL TRACES ON TOP LAYER NEED 50 ohm +/-5% IMPEDANCE" at 4657.81,-420.43 h75
  text "MIL, HOLES" at 11816.46,-513.6 h60
  text "+/-" at 11424,-522.19 h60
  text "+/-" at 12278,-522.19 h60
  text "REGISTRATION TOLERANCES:" at 9908.23,-523.25 h60
  text "METAL" at 11108,-523.25 h60
  text "5" at 11684.2,-523.25 h60
  text "3" at 12517.2,-523.25 h60
  text "MIL" at 12633.46,-523.25 h60
  text "WITH 8.51 MIL COPLANAR SPACING" at 4805.93,-593.51 h75
  text "HOLE SIZE TOLERANCE (UNLESS OTHERWISE SPECIFIED):" at 9908.23,-621.57 h60
  text "+/-" at 12278,-624.44 h60
  text "3" at 12517.2,-625.5 h60
  text "MIL" at 12633.46,-625.5 h60
  text "MATERIAL:" at 9833.46,-763.15 h60
  text "5. ALL 11.61 MIL TRACES ON TOP LAYER NEED 50 ohm +/-5% IMPEDANCE" at 4667.81,-815.59 h75
  text "FR-4 High Tg" at 10819.9,-891.68 h60
  text "X" at 11564.46,-899.66 h60
  text "Megtron6+FR4 High tg" at 12060.38,-900.61 h45
  text "FR-408" at 10254.46,-904.18 h60
  text "OTHER" at 11742.46,-904.18 h60
  text "62 MIL (1.6mm) +/-10%" at 10574.56,-1047.21 h60
  text "X" at 10454.46,-1049.66 h60
  text "THICKNESS:" at 9908.23,-1055.43 h60
  text "OTHER" at 11859.46,-1055.43 h60
  text "6. ALL 9.94 MIL TRACES ON BOTTOM LAYER NEED 50 ohm +/-5% IMPEDANCE" at 4667.81,-1080.48 h75
  text "TOLERANCE:" at 9908.23,-1193.75 h60
  text "X" at 10756.46,-1193.75 h60
  text "ANSI IPC-6012 TYPE 3 CLASS 2" at 10934.48,-1193.75 h60
  text "7. ALL 11.98 MIL TRACES WITH 12.02 MIL AIRGAP ON TOP LAYER" at 4657.81,-1317.98 h75
  text "OTHER +/-" at 10934.46,-1337.94 h60
  text "BOW & TWIST:" at 9908.23,-1483.13 h60
  text "X" at 10756.46,-1483.13 h60
  text "ANSI IPC-6012 TYPE 3 CLASS 2" at 10934.48,-1483.13 h60
  text "NEED 90 ohm +/-5% IMPEDANCE WITH 8.01 MIL COPLANAR SPACING" at 4805.93,-1491.05 h75
  text "OTHER +/-" at 10934.46,-1629.82 h60
  text "8. ALL 10.57 MIL TRACES WITH 13.43 MIL AIRGAP ON BOTTOM LAYER" at 4667.81,-1663.85 h75
  text "DRILLING:" at 9833.46,-1760.44 h60
  text "NEED 90 ohm +/-5% IMPEDANCE WITH 8.71 MIL COPLANAR SPACING" at 4805.93,-1837.37 h75
  text "NC_DRILL FILES" at 11594.46,-1865.63 h60
  text "REFERENCE:" at 9908.23,-1869.57 h60
  text "X" at 10565.46,-1869.66 h60
  text "AS SHOWN" at 10743.46,-1869.57 h60
  text "X" at 11466.46,-1869.57 h60
  text "OTHER" at 11892.46,-2011.82 h60
  text "PTH COPPER THICKNESS:" at 9907.91,-2015.35 h60
  text "X" at 11047.14,-2015.35 h60
  text "20-30 um" at 11175.14,-2015.35 h60
  text "9. ALL 8.85 MIL TRACES WITH 9.15 MIL AIRGAP ON TOP LAYER" at 4678.34,-2099.2 h75
  text "BOARD FINISH:" at 9833.46,-2162.95 h60
  text "NEED 100 ohm +/-5% IMPEDANCE WITH 8.575 MIL COPLANAR SPACING" at 4804.94,-2272.72 h75
  text "SILKSCREEN:" at 9988.68,-2273.07 h60
  text "X" at 10946.46,-2273.07 h60
  text "TOP" at 11063.46,-2273.07 h60
  text "X" at 11456.46,-2273.07 h60
  text "BOTTOM" at 11574.46,-2273.07 h60
  text "SILKSCREEN COLOR:" at 9988.68,-2428.26 h60
  text "X" at 10945.46,-2428.26 h60
  text "WHITE" at 11063.46,-2428.26 h60
  text "OTHER" at 11574.46,-2428.26 h60
  text "X" at 11076.46,-2571.71 h60
  text "GREEN" at 11194.46,-2571.71 h60
  text "OTHER" at 11812.46,-2571.71 h60
  text "FAB NOTES :" at 4817.68,-2573.81 h75
  text "SOLDER RESIST COLOR:" at 9988.68,-2578.58 h60
  text "X" at 11076.46,-2725.96 h60
  text "MATTE" at 11194.46,-2725.96 h60
  text "SEMI-GLOSS" at 11812,-2726.6 h60
  text "10. ALL VIAS BELOW 20 MIL DRILL VIAS NEED SOLDER MASK" at 4748,-2785.03 h75
  text "IMMERSION GOLD (ENIG)" at 10894.46,-2898.73 h60
  text "ENEPIG" at 12232,-2905.95 h60
  text "SURFACE FINISH:" at 9833.46,-2906.95 h60
  text "X" at 10716.46,-2906.95 h60
  text "PLUGGING FROM BOTTOM SIDE." at 4934.19,-2955.66 h75
  text "IMM. TIN/SILVER OR EQUIV" at 10163,-3044.27 h60
  text "OTHER" at 11594.46,-3048.21 h60
  text "11. ALL HOLES SHOULD BE FHS." at 4748,-3132.1 h75
  text "ARRAY/PANEL:" at 9833.46,-3203.58 h60
  text "X" at 10716.46,-3207.77 h60
  text "CUT AND TRIM PER M1 BOARD OUTLINE" at 10894.46,-3211.81 h60
  text "12. NO VENDOR LOGO OR NAME ON THE BOARD." at 4748,-3312.67 h75
  text "N.C. ROUTE" at 10894.46,-3347.77 h60
  text "V. SCORE" at 11760.46,-3347.77 h60
  text "13. REMOVE ALL UNUSED PADS IN ALL INNER LAYERS" at 4748,-3474.33 h75
  text "CERTIFICATION:" at 9833.46,-3476.9 h60
  text "MATERIALS AND WORKMANSHIP FOR ALL PCBS" at 10558.46,-3476.9 h60
  text "TO MEET OR EXCEED THE REQUIREMENTS OF:" at 10558.46,-3570.96 h60
  text "14. CLIP THE SILK ON NO MASK AREA." at 4748,-3650.75 h75
  text "X" at 10195.97,-3699.59 h60
  text "ANSI IPC-A-600F CLASS ->" at 10323.96,-3699.59 h60
  text "X" at 11971.97,-3699.59 h60
  text "2" at 12081.96,-3699.59 h60
  text "1" at 11766.96,-3701.09 h60
  text "3" at 12435.96,-3701.09 h60
  text "15. DO NOT BREAK THE BOARDS AFTER FABRICATION." at 4748,-3821.29 h75
  text "X" at 11007.97,-3847.28 h60
  text "RoHS" at 11135.96,-3847.28 h60
  text "OTHER" at 11780.36,-3847.28 h60
  text "PER ORDER" at 12177.42,-3847.28 h60
  text "ALL BOARDS MUST MEET OR EXCEED UL94-V0 REQUIREMENTS." at 9861,-4001.1 h60
  text "PCB MUST BEAR THE UL94V-0 UL REGISTERED MATERIAL ID NUMBER" at 9861,-4117.17 h60
  text "ADDITIONAL REQUIREMENTS:" at 9833.46,-4286.59 h60
  text "MICROSECTION:" at 9908.23,-4393.72 h60
  text "YES" at 10813.96,-4393.72 h60
  text "REQUIRED" at 11675.46,-4538.05 h60
  text "BARE BOARD ELEC. TEST:" at 9908.23,-4540.91 h60
  text "NONE" at 11213.96,-4540.91 h60
  text "X" at 11557.46,-4540.91 h60
  text "PER ORDER" at 12267.46,-4540.91 h60
  text "XX MIL VIAS REQUIRE NON-CONDUCTIVE FILL AND PLANARIZE" at 10076.38,-4745.85 h59
  text "XX MIL VIAS REQUIRE CONDUCTIVE FILL AND PLANARIZE" at 10084.38,-4849.83 h60
  text "OUTER XX MIL TRACES REQUIRE 50 OHM SINGLE-ENDED IMPEDANCE" at 10083.39,-5013.21 h58
  text "LAYER 2 & 3 (INNER LAYERS) XX MIL WIDE, XX MIL SPACE / TRACES REQUIRE 100 OHM DIFFERENTIAL IMPEDANCE" at 10075.39,-5248.93 h60
  text ".Layer_Name" at -923,-6999.16 h60
M11 Gerber Information:
  circle w10: c4296.99,-434.47 r65
  circle w10: c4296.6,-434.41 r34.79
  circle w10: c-278.12,-434.47 r65
  circle w10: c-278.52,-434.41 r34.79
  circle w10: c-139.21,4868.86 r34.79
  circle w10: c-138.82,4868.81 r65
  lines w10: -1792,-7070.84 4808,-7070.84 ; -1792,-6867.5 4810,-6867.5 ; -1792,-6664.17 -1792,-7274.17 2213,-7274.17 4810,-7274.17 4810,-6664.17 -1791.5,-6664.17 -1791.5,-7274.17 -216,-7274.17 ; -385.74,-433.67 -182.48,-433.67 ; -279.72,-527.74 -279.72,-336.41 ; -246.44,4869.61 -43.18,4869.61 ; -140.41,4775.54 -140.41,4966.86 ; 673,-7274.17 673,-6664.17 ; 1940,-6867.5 1940,-6664.17 ; 2780,-6867.5 2780,-6664.17 ; 3402,-7280.67 3402,-7077.84 ; 4189.37,-433.67 4392.63,-433.67 ; 4295.39,-527.74 4295.39,-336.41
  text "ALL ARTWORK VIEWED FROM TOP SIDE" at -1728.5,-6796.34 h60
  text "BOARD #:" at 748,-6796.34 h60
  text "LMH1239" at 1293.5,-6796.34 h60
  text "REV:" at 2138,-6796.34 h60
  text ".PCB_Rev" at 2429.5,-6796.34 h60
  text "SVN REV:" at 2976,-6796.34 h60
  text ".VersionControl_RevNumber" at 3482,-6796.34 h60
  text "LAYER NAME =" at -1728.5,-6999.16 h60
  text "TID #:" at 748,-6999.67 h60
  text ".TID" at 1293.5,-6999.67 h60
  text ".plot_File_Name" at -1054.78,-7194.19 h40
  text "PLOT NAME =" at -1728.5,-7205.01 h60
  text "GENERATED    :" at 750,-7205.01 h60
  text ".Print_Date" at 1619.5,-7205.01 h60
  text ".Print_Time" at 2348.5,-7205.01 h60
  text "TEXAS INSTRUMENTS" at 3613,-7205.01 h60
M12 Stackup:
  drawing of 301 lines, arcs and shapes, not listed
  text "STACK UP :" at 4794.72,2942.89 h75
  text "Layer" at 4858.47,2789.84 h60
  text "Name" at 5268.38,2789.84 h60
  text "Material" at 6198.13,2789.84 h60
  text "Thickness" at 7057.89,2789.84 h60
  text "Constant" at 7707.73,2789.84 h60
  text "Board Layer Stack" at 8277.59,2789.84 h60
  text "Top Overlay" at 5268.38,2669.84 h60
  text "Top Solder" at 5268.38,2549.84 h60
  text "Solder Resist" at 6198.13,2549.84 h60
  text "0.40mil" at 7057.89,2549.84 h60
  text "3.5" at 7707.73,2549.84 h60
  text "0.5oz + PLATING" at 9560.27,2439.53 h60
  text "1" at 4858.47,2429.84 h60
  text "Top Layer" at 5268.38,2429.84 h60
  text "Copper" at 6198.13,2429.84 h60
  text "1.40mil" at 7057.89,2429.84 h60
  text "Dielectric 1" at 5268.38,2309.84 h60
  text "Megtron6" at 6198.13,2309.84 h60
  text "5.48mil" at 7057.89,2309.84 h60
  text "3.19" at 7707.73,2309.84 h60
  text "2" at 4858.47,2189.84 h60
  text "L02_GND" at 5268.38,2189.84 h60
  text "Copper" at 6198.13,2189.84 h60
  text "1.40mil" at 7057.89,2189.84 h60
  text "Dielectric 2" at 5268.38,2069.84 h60
  text "FR-4 High Tg" at 6198.13,2069.84 h60
  text "44.81mil" at 7057.89,2069.84 h60
  text "3.89" at 7707.73,2069.84 h60
  text "3" at 4858.47,1949.84 h60
  text "L03_PWR" at 5268.38,1949.84 h60
  text "Copper" at 6198.13,1949.84 h60
  text "1.40mil" at 7057.89,1949.84 h60
  text "Dielectric 3" at 5268.38,1829.84 h60
  text "FR-4 High Tg" at 6198.13,1829.84 h60
  text "5.50mil" at 7057.89,1829.84 h60
  text "3.87" at 7707.73,1829.84 h60
  text "0.5oz + PLATING" at 9560.27,1719.53 h60
  text "4" at 4858.47,1709.84 h60
  text "Bottom Layer" at 5268.38,1709.84 h60
  text "Copper" at 6198.13,1709.84 h60
  text "1.40mil" at 7057.89,1709.84 h60
  text "Bottom Solder" at 5268.38,1589.84 h60
  text "Solder Resist" at 6198.13,1589.84 h60
  text "0.40mil" at 7057.89,1589.84 h60
  text "3.5" at 7707.73,1589.84 h60
  text "Bottom Overlay" at 5268.38,1469.84 h60
  text "Total board thickness:" at 4858.47,1349.84 h60
  text "62.20mil" at 7057.89,1349.84 h60
  text ".Layer_Name" at -923,-6999.16 h60
M13 Component Bodies Top:
  text ".Layer_Name" at -923,-6999.16 h60
M14 Component Bodies Bottom:
  text ".Layer_Name" at -923,-6999.16 h60
M15 Courtyards Top:
  text ".Layer_Name" at -923,-6999.16 h60
M16 Courtyards Bottom:
  text ".Layer_Name" at -923,-6999.16 h60
Drill Drawing:
  circle w10: c4867.25,3531.66 r33.33
  circle w10: c4867.25,3381.66 r20
  circle w10: c4867.25,3381.66 r33.33
  lines w10: 4833.92,3664.99 4850.58,3664.99 4867.25,3648.33 4883.92,3664.99 4900.58,3664.99 4883.92,3681.66 4900.58,3698.33 4883.92,3698.33 4867.25,3714.99 4850.58,3698.33 4833.92,3698.33 4850.58,3681.66 4833.92,3664.99 ; 4833.92,3864.99 4900.58,3864.99 4867.25,3798.33 4833.92,3864.99 ; 4833.92,3948.33 4900.58,3948.33 4900.58,4014.99 4833.92,4014.99 4833.92,3948.33 ; 4833.92,4098.33 4867.25,4114.99 4900.58,4098.33 4883.92,4131.66 4900.58,4164.99 4867.25,4148.33 4833.92,4164.99 4850.58,4131.66 4833.92,4098.33 ; 4833.92,4248.33 4867.25,4264.99 4900.58,4248.33 4883.92,4281.66 4900.58,4314.99 4867.25,4298.33 4833.92,4314.99 4850.58,4281.66 4833.92,4248.33 ; 4833.92,4398.33 4833.92,4414.99 4850.58,4431.66 4833.92,4448.33 4833.92,4464.99 4850.58,4464.99 4867.25,4448.33 4883.92,4464.99 4900.58,4464.99 4900.58,4448.33 4883.92,4431.66 4900.58,4414.99 4900.58,4398.33 4883.92,4398.33 4867.25,4414.99 4850.58,4398.33 4833.92,4398.33 ; 4833.92,4564.99 4850.58,4564.99 4867.25,4548.33 4883.92,4564.99 4900.58,4564.99 4883.92,4581.66 4900.58,4598.33 4883.92,4598.33 4867.25,4614.99 4850.58,4598.33 4833.92,4598.33 4850.58,4581.66 4833.92,4564.99 ; 4833.92,4714.99 4850.58,4714.99 4850.58,4698.33 4883.92,4698.33 4883.92,4714.99 4900.58,4714.99 4900.58,4748.33 4883.92,4748.33 4883.92,4764.99 4850.58,4764.99 4850.58,4748.33 4833.92,4748.33 4833.92,4714.99 ; 4833.92,4848.33 4900.58,4848.33 4900.58,4914.99 4833.92,4914.99 4833.92,4848.33 ; 4833.92,5031.66 4867.25,4998.33 4900.58,5031.66 4867.25,5064.99 4833.92,5031.66 ; 4847.25,3851.66 4887.25,3851.66 4867.25,3811.66 4847.25,3851.66 ; 4847.25,3961.66 4887.25,3961.66 4887.25,4001.66 4847.25,4001.66 4847.25,3961.66 ; 4847.25,4261.66 4867.25,4271.66 4887.25,4261.66 4877.25,4281.66 4887.25,4301.66 4867.25,4291.66 4847.25,4301.66 4857.25,4281.66 4847.25,4261.66 ; 4847.25,4571.66 4857.25,4571.66 4867.25,4561.66 4877.25,4571.66 4887.25,4571.66 4877.25,4581.66 4887.25,4591.66 4877.25,4591.66 4867.25,4601.66 4857.25,4591.66 4847.25,4591.66 4857.25,4581.66 4847.25,4571.66
  lines w15: 4774.12,3303.33 11172.39,3303.33 ; 4774.12,5103.33 11172.39,5103.33 ; 5325,3153.33 5325,5253.33 ; 5914.85,3153.33 5914.85,5253.33 ; 7064.51,3153.33 7064.51,5253.33 ; 7570.38,3153.33 7570.38,5253.33 ; 8304.19,3153.33 8304.19,5253.33 ; 9803.74,3153.33 9803.74,5253.33 ; 10393.59,3153.33 10393.59,5253.33 ; 4774.12,3153.33 11172.39,3153.33 11172.39,5253.33 4774.12,5253.33 4774.12,3153.33
  text "DRILL TABLE :" at 4770.96,5336.26 h75
  text "Symbol" at 4864.12,5148.33 h72
  text "Count" at 5370,5148.33 h72
  text "Hole Size" at 5959.85,5148.33 h72
  text "Plated" at 7109.51,5148.33 h72
  text "Hole Type" at 7615.38,5148.33 h72
  text "Drill Layer Pair" at 8349.19,5148.33 h72
  text "Via/Pad" at 9848.74,5148.33 h72
  text "Tolerance" at 10438.59,5148.33 h72
  text "4" at 5370,4998.33 h60
  text "7.87mil (0.200mm)" at 5959.85,4998.33 h60
  text "PTH" at 7109.51,4998.33 h60
  text "Round" at 7615.38,4998.33 h60
  text "Top Layer - Bottom Layer" at 8349.19,4998.33 h60
  text "Via" at 9848.74,4998.33 h60
  text "+2/-2 mil" at 10438.59,4998.33 h60
  text "4" at 5370,4848.33 h60
  text "35.43mil (0.900mm)" at 5959.85,4848.33 h60
  text "NPTH" at 7109.51,4848.33 h60
  text "Round" at 7615.38,4848.33 h60
  text "Top Layer - Bottom Layer" at 8349.19,4848.33 h60
  text "Pad" at 9848.74,4848.33 h60
  text "+2/-0 mil" at 10438.59,4848.33 h60
  text "4" at 5370,4698.33 h60
  text "51.97mil (1.320mm)" at 5959.85,4698.33 h60
  text "PTH" at 7109.51,4698.33 h60
  text "Round" at 7615.38,4698.33 h60
  text "Top Layer - Bottom Layer" at 8349.19,4698.33 h60
  text "Pad" at 9848.74,4698.33 h60
  text "+2/-2 mil" at 10438.59,4698.33 h60
  text "4" at 5370,4548.33 h60
  text "125.98mil (3.200mm)" at 5959.85,4548.33 h60
  text "NPTH" at 7109.51,4548.33 h60
  text "Round" at 7615.38,4548.33 h60
  text "Top Layer - Bottom Layer" at 8349.19,4548.33 h60
  text "Pad" at 9848.74,4548.33 h60
  text "+3/-3 mil" at 10438.59,4548.33 h60
  text "7" at 5370,4398.33 h60
  text "39.37mil (1.000mm)" at 5959.85,4398.33 h60
  text "PTH" at 7109.51,4398.33 h60
  text "Round" at 7615.38,4398.33 h60
  text "Top Layer - Bottom Layer" at 8349.19,4398.33 h60
  text "Pad" at 9848.74,4398.33 h60
  text "+2/-2 mil" at 10438.59,4398.33 h60
  text "9" at 5370,4248.33 h60
  text "10.10mil (0.257mm)" at 5959.85,4248.33 h60
  text "PTH" at 7109.51,4248.33 h60
  text "Round" at 7615.38,4248.33 h60
  text "Top Layer - Bottom Layer" at 8349.19,4248.33 h60
  text "Via" at 9848.74,4248.33 h60
  text "+2/-2 mil" at 10438.59,4248.33 h60
  text "16" at 5370,4098.33 h60
  text "45.30mil (1.151mm)" at 5959.85,4098.33 h60
  text "PTH" at 7109.51,4098.33 h60
  text "Round" at 7615.38,4098.33 h60
  text "Top Layer - Bottom Layer" at 8349.19,4098.33 h60
  text "Pad" at 9848.74,4098.33 h60
  text "+2/-2 mil" at 10438.59,4098.33 h60
  text "24" at 5370,3948.33 h60
  text "16.00mil (0.406mm)" at 5959.85,3948.33 h60
  text "PTH" at 7109.51,3948.33 h60
  text "Round" at 7615.38,3948.33 h60
  text "Top Layer - Bottom Layer" at 8349.19,3948.33 h60
  text "Via" at 9848.74,3948.33 h60
  text "+2/-2 mil" at 10438.59,3948.33 h60
  text "54" at 5370,3798.33 h60
  text "10.00mil (0.254mm)" at 5959.85,3798.33 h60
  text "PTH" at 7109.51,3798.33 h60
  text "Round" at 7615.38,3798.33 h60
  text "Top Layer - Bottom Layer" at 8349.19,3798.33 h60
  text "Via" at 9848.74,3798.33 h60
  text "+2/-2 mil" at 10438.59,3798.33 h60
  text "84" at 5370,3648.33 h60
  text "40.00mil (1.016mm)" at 5959.85,3648.33 h60
  text "PTH" at 7109.51,3648.33 h60
  text "Round" at 7615.38,3648.33 h60
  text "Top Layer - Bottom Layer" at 8349.19,3648.33 h60
  text "Pad" at 9848.74,3648.33 h60
  text "+2/-2 mil" at 10438.59,3648.33 h60
  text "224" at 5370,3498.33 h60
  text "8.10mil (0.206mm)" at 5959.85,3498.33 h60
  text "PTH" at 7109.51,3498.33 h60
  text "Round" at 7615.38,3498.33 h60
  text "Top Layer - Bottom Layer" at 8349.19,3498.33 h60
  text "Via" at 9848.74,3498.33 h60
  text "+2/-2 mil" at 10438.59,3498.33 h60
  text "278" at 5370,3348.33 h60
  text "8.00mil (0.203mm)" at 5959.85,3348.33 h60
  text "PTH" at 7109.51,3348.33 h60
  text "Round" at 7615.38,3348.33 h60
  text "Top Layer - Bottom Layer" at 8349.19,3348.33 h60
  text "Via" at 9848.74,3348.33 h60
  text "+2/-2 mil" at 10438.59,3348.33 h60
  text "712 Total" at 5370,3198.33 h60
  text ".Layer_Name" at -923,-6999.16 h60
M17 Embedded Cavity:
  text ".Layer_Name" at -923,-6999.16 h60
M18 Embedded Assembly:
  text ".Layer_Name" at -923,-6999.16 h60
M19 Embedded Keepout:
  text ".Layer_Name" at -923,-6999.16 h60

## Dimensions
0,4500 to 0,0 on M2 Board Dimensions
0,4500 to 4000,4500 on M2 Board Dimensions
4000,0 to 4000,4500 on M2 Board Dimensions
-1500,-6540.67 to -500,-6540.67 on M2 Board Dimensions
